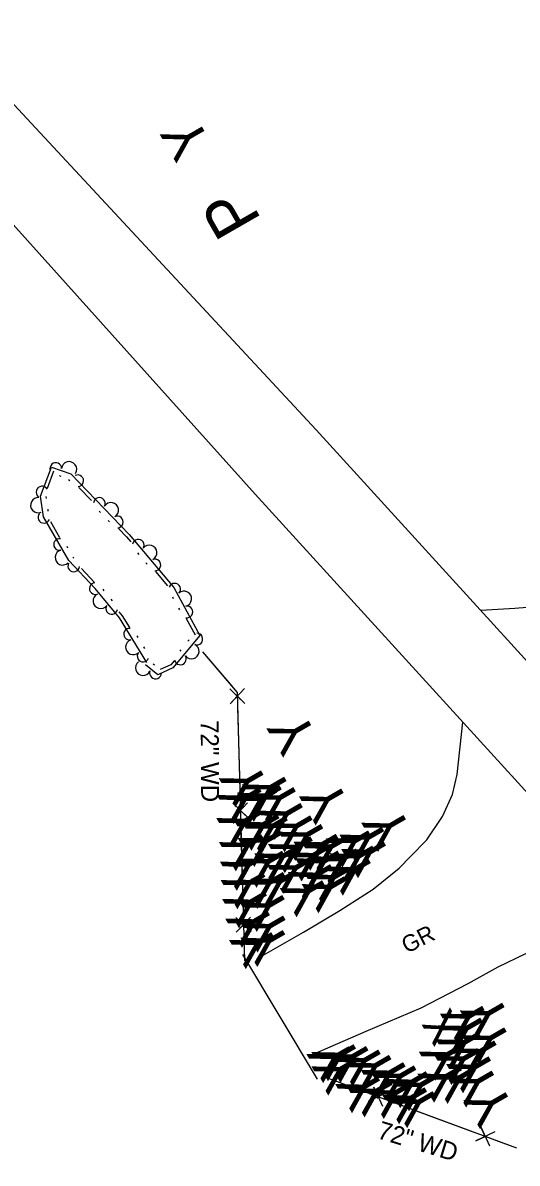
# Model space of a CAD drawing. Extents: x 2030130 to 2036320, y 723205 to 762423.
# Drawn here: x 2034222.4 to 2034332.5, y 759439.7 to 759693.3 of the extents above; entities that cross this region are included whole.
import ezdxf

# ---------------------------------------------------------------- set-up
doc = ezdxf.new("R2010")
doc.units = 0
for name, color, linetype in [('Draft_Station Labels Major', 7, 'Continuous'), ('Draft_Station Tics Major', 7, 'Continuous'), ('Exist Terrain Model Ground Surface', 7, 'Continuous'), ('Old_Level_23', 7, 'Continuous'), ('Old_Level_28', 7, 'Continuous'), ('Prop Horizontal Alignment Ramp', 7, 'Continuous')]:
    doc.layers.add(name, color=color, linetype=linetype)

msp = doc.modelspace()

# ---------------------------------------------------------------- linework, layer by layer
at = {"layer": 'Draft_Station Labels Major'}
for points in [[(2034193.98, 759703.56), (2034287.73, 759602.79), (2034370.61, 759511.86), (2034419.72, 759458.43), (2034445.33, 759432.37), (2034471.55, 759407.33), (2034497.11, 759385.14), (2034517.55, 759368.37), (2034528.08, 759360.37)], [(2034406.4, 759697.05), (2034404.29, 759687.94), (2034402.24, 759679.54), (2034400.98, 759670.76), (2034398.6, 759659.72), (2034394.4, 759646.76), (2034391.51, 759636.74), (2034390.8, 759626.41), (2034391.91, 759617.38), (2034392.01, 759607.6), (2034388.72, 759601.52), (2034384.63, 759597.38), (2034380.26, 759590.7), (2034376.86, 759584.48), (2034371.89, 759577.33), (2034367.26, 759572.7), (2034359.83, 759567.87), (2034353.85, 759564.53), (2034347.15, 759563.4), (2034340.28, 759563.68), (2034331.95, 759563.03), (2034324.37, 759562.59)], [(2034181.13, 759691.91), (2034274.16, 759588.48), (2034357, 759497.6), (2034406.36, 759443.89), (2034432.44, 759417.35), (2034459.25, 759391.75), (2034485.39, 759369.06), (2034506.34, 759351.88), (2034517.18, 759343.65)], [(2034274.47, 759485.08), (2034284.85, 759491.04), (2034292.96, 759495.88), (2034300.4, 759500.6), (2034306.21, 759505.3), (2034308.71, 759507.9), (2034312.37, 759511.61), (2034315.84, 759516.74), (2034318.06, 759521.68), (2034319.08, 759526.13), (2034320.38, 759537.78)], [(2034371.58, 759481.74), (2034358.91, 759486.23), (2034354.02, 759487.37), (2034349.95, 759488.15), (2034345.68, 759488.73), (2034339.79, 759487.64), (2034334.3, 759486.19), (2034328.17, 759483.26), (2034321.51, 759479.53), (2034310.99, 759474.16), (2034298.75, 759468.94), (2034287.34, 759463.98)]]:
    msp.add_lwpolyline(points, dxfattribs=at)
at = {"layer": 'Draft_Station Tics Major'}
for points in [[(2034250.03, 759551.04), (2034243.94, 759560.93), (2034238.53, 759567.45), (2034232.63, 759573.68), (2034227.01, 759583.43), (2034226.35, 759588.02), (2034228.75, 759594.49), (2034233.09, 759593.02), (2034246.09, 759579.5), (2034256, 759567.69), (2034261.77, 759557.02), (2034255.82, 759549.82), (2034252.42, 759548.28), (2034249.68, 759550.49)], [(2034227.88, 759589.8), (2034229.31, 759593.64)], [(2034230.5, 759592.6), (2034230.89, 759592.47)], [(2034232.58, 759591.76), (2034232.87, 759591.47)], [(2034234.87, 759589.98), (2034237.71, 759587.03)], [(2034227.66, 759587.53), (2034227.6, 759587.94)], [(2034228.07, 759584.69), (2034228.01, 759585.1)], [(2034239.41, 759584.67), (2034239.69, 759584.38)], [(2034230.66, 759578.75), (2034228.61, 759582.3)], [(2034241.4, 759582.6), (2034241.69, 759582.31)], [(2034243.69, 759580.82), (2034245.48, 759578.96), (2034246.42, 759577.84)], [(2034232.45, 759576.47), (2034232.24, 759576.82)], [(2034233.78, 759574.26), (2034233.63, 759574.42)], [(2034247.95, 759575.38), (2034248.21, 759575.06)], [(2034249.79, 759573.18), (2034250.06, 759572.86)], [(2034238.27, 759568.92), (2034235.45, 759571.9)], [(2034251.95, 759571.24), (2034254.59, 759568.1)], [(2034240.51, 759566.98), (2034240.25, 759567.3)], [(2034255.7, 759565.65), (2034255.9, 759565.29)], [(2034242.35, 759564.77), (2034242.09, 759565.09)], [(2034257.07, 759563.13), (2034257.26, 759562.77)], [(2034246.21, 759558.81), (2034244.6, 759561.41), (2034243.86, 759562.3)], [(2034258.79, 759560.8), (2034260.75, 759557.19)], [(2034248.06, 759556.58), (2034247.85, 759556.93)], [(2034259.41, 759556.08), (2034259.14, 759555.77)], [(2034249.57, 759554.13), (2034249.35, 759554.48)], [(2034257.58, 759553.87), (2034257.32, 759553.56)], [(2034251.74, 759550.41), (2034251.42, 759550.67)], [(2034256.06, 759551.4), (2034255.31, 759550.49), (2034253, 759549.45)]]:
    msp.add_lwpolyline(points, dxfattribs=at)
for centre, radius, start, end in [((2034229.73, 759594.16), 1.3, 359.6468, 200.4434), ((2034232.71, 759594.01), 1.69, 327.1756, 175.2481), ((2034234.61, 759591.44), 1.3, 274.6697, 115.4663), ((2034226.68, 759588.93), 1.3, 30.4451, 231.2417), ((2034225.81, 759586.02), 1.69, 84.1627, 292.2352), ((2034239.44, 759586.41), 1.3, 332.3362, 173.1327), ((2034242.02, 759584.91), 1.69, 299.865, 147.9375), ((2034227.08, 759583.31), 1.3, 138.4082, 339.2048), ((2034243.42, 759582.28), 1.3, 274.6697, 115.4663), ((2034230.56, 759577.27), 1.3, 80.7418, 281.5383), ((2034248.1, 759577.11), 1.3, 328.4294, 169.2259), ((2034231.28, 759574.38), 1.69, 105.937, 314.0095), ((2034250.57, 759575.44), 1.69, 295.9582, 144.0307), ((2034233.73, 759572.52), 1.3, 151.8397, 352.6363), ((2034251.79, 759572.71), 1.3, 270.7629, 111.5595), ((2034238.52, 759567.46), 1.3, 94.1733, 294.9698), ((2034256.2, 759567.32), 1.3, 316.8309, 157.6275), ((2034239.72, 759564.73), 1.69, 115.6449, 323.7174), ((2034258.29, 759565.19), 1.69, 284.3597, 132.4322), ((2034242.19, 759563.04), 1.3, 148.1161, 348.9127), ((2034258.93, 759562.27), 1.3, 259.1644, 99.961), ((2034246.15, 759557.33), 1.3, 82.3998, 283.1964), ((2034246.96, 759554.45), 1.69, 107.5951, 315.6676), ((2034261.14, 759556.25), 1.3, 248.8652, 89.6617), ((2034249.17, 759552.44), 1.3, 140.0663, 340.8629), ((2034259.94, 759553.51), 1.69, 216.394, 64.4665), ((2034249.17, 759549.84), 1.69, 127.0823, 335.1548), ((2034257.48, 759551.82), 1.3, 191.1987, 31.9953), ((2034251.92, 759548.68), 1.3, 159.5535, 0.3501)]:
    msp.add_arc(centre, radius, start, end, dxfattribs=at)
at = {"layer": 'Exist Terrain Model Ground Surface'}
msp.add_line((2034288.01, 759458.38), (2034271.37, 759486.04), dxfattribs=at)
for points in [[(2034262.41, 759553.4), (2034270.11, 759544.38), (2034271.73, 759484.69)], [(2034262.41, 759553.4), (2034269.07, 759545.6)], [(2034268.45, 759545.13), (2034271.82, 759541.93), (2034270.14, 759543.53), (2034268.54, 759541.85), (2034271.73, 759545.21)], [(2034270.2, 759541.07), (2034270.48, 759530.82)], [(2034270.48, 759530.82), (2034270.76, 759520.57)], [(2034269.14, 759519.71), (2034272.51, 759516.52), (2034270.82, 759518.11), (2034269.23, 759516.43), (2034272.42, 759519.8)], [(2034270.89, 759515.65), (2034271.17, 759505.4)], [(2034271.17, 759505.4), (2034271.45, 759495.16)], [(2034269.83, 759494.29), (2034273.2, 759491.1), (2034271.51, 759492.7), (2034269.92, 759491.01), (2034273.11, 759494.38)], [(2034271.58, 759490.24), (2034271.73, 759484.69)], [(2034289.58, 759458.87), (2034332.32, 759443.05)], [(2034289.58, 759458.87), (2034299.19, 759455.31)], [(2034303.61, 759455.42), (2034299.39, 759453.49), (2034301.5, 759454.46), (2034300.53, 759456.56), (2034302.47, 759452.35)], [(2034303.81, 759453.6), (2034313.42, 759450.04)], [(2034313.42, 759450.04), (2034323.04, 759446.48)], [(2034327.45, 759446.6), (2034323.24, 759444.66), (2034325.35, 759445.63), (2034324.38, 759447.74), (2034326.32, 759443.52)], [(2034327.65, 759444.78), (2034332.32, 759443.05)]]:
    msp.add_lwpolyline(points, dxfattribs=at)

# ---------------------------------------------------------------- texts
at = {"layer": 'Draft_Station Tics Major'}
for s, height, p in [('Y', 9.02, (2034264.55, 759666.27)), ('Y', 9.02, (2034288.32, 759534.12)), ('Y', 9.02, (2034277.7, 759523.06)), ('Y', 9.02, (2034282.85, 759521.66)), ('Y', 9.02, (2034277.27, 759519.32)), ('Y', 9.02, (2034280.72, 759519.09)), ('Y', 9.02, (2034281.78, 759519.81)), ('Y', 9.02, (2034284.9, 759519.35)), ('Y', 9.02, (2034295.55, 759519.03)), ('Y', 9.02, (2034277.16, 759514.19)), ('Y', 9.02, (2034281.25, 759513.4)), ('Y', 9.02, (2034286.46, 759515.83)), ('Y', 9.02, (2034283.12, 759512.91)), ('Y', 9.02, (2034288.63, 759513.06)), ('Y', 9.02, (2034291.01, 759511.14)), ('Y', 9.02, (2034309.43, 759513.14)), ('Y', 9.02, (2034277.77, 759508.84)), ('Y', 9.02, (2034281.9, 759509.79)), ('Y', 9.02, (2034288.68, 759508.4)), ('Y', 9.02, (2034294.34, 759508.96)), ('Y', 9.02, (2034296.36, 759508.5)), ('Y', 9.02, (2034301.54, 759509.71)), ('Y', 9.02, (2034304.57, 759510.51)), ('Y', 9.02, (2034285.61, 759506.35)), ('Y', 9.02, (2034292.41, 759506.57)), ('Y', 9.02, (2034302.45, 759506.33)), ('Y', 9.02, (2034304.97, 759507.3)), ('Y', 9.02, (2034277.98, 759504.49)), ('Y', 9.02, (2034282.37, 759505.18)), ('Y', 9.02, (2034288.46, 759503.79)), ('Y', 9.02, (2034294.74, 759505.23)), ('Y', 9.02, (2034298.81, 759505.67)), ('Y', 9.02, (2034301.6, 759503.42)), ('Y', 9.02, (2034284.94, 759500.76)), ('Y', 9.02, (2034293.08, 759502.2)), ('Y', 9.02, (2034296.92, 759501.67)), ('Y', 9.02, (2034278.12, 759500.4)), ('Y', 9.02, (2034282.57, 759500.47)), ('Y', 9.02, (2034291.3, 759498.62)), ('Y', 9.02, (2034296.17, 759499.5)), ('Y', 9.02, (2034278.46, 759496.2)), ('Y', 9.02, (2034282.44, 759495.36)), ('Y', 9.02, (2034279.14, 759491.83)), ('Y', 9.02, (2034282.62, 759490.78)), ('Y', 9.02, (2034279.99, 759487.08)), ('Y', 9.02, (2034282.55, 759487.55)), ('X', 7.38, (2034320.65, 759468.82)), ('Y', 9.02, (2034326.94, 759470.7)), ('Y', 9.02, (2034331.39, 759471.39)), ('Y', 9.02, (2034326.52, 759468.08)), ('Y', 9.02, (2034331.84, 759465.91)), ('Y', 9.02, (2034326.05, 759464.96)), ('Y', 9.02, (2034329.61, 759462.99)), ('Y', 9.02, (2034297.22, 759461.72)), ('Y', 9.02, (2034298.3, 759462.16)), ('Y', 9.02, (2034301.07, 759461.76)), ('Y', 9.02, (2034303.8, 759460.97)), ('Y', 9.02, (2034322.24, 759462.25)), ('Y', 9.02, (2034325.8, 759461.29)), ('Y', 9.02, (2034298.36, 759458.95)), ('Y', 9.02, (2034306.19, 759459.79)), ('Y', 9.02, (2034309.34, 759458.17)), ('Y', 9.02, (2034328.36, 759459.47)), ('Y', 9.02, (2034303.64, 759455.04)), ('Y', 9.02, (2034311.73, 759457.45)), ('Y', 9.02, (2034314.38, 759456.16)), ('Y', 9.02, (2034316.32, 759455.49)), ('Y', 9.02, (2034321.91, 759457.36)), ('Y', 9.02, (2034324.92, 759457.1)), ('Y', 9.02, (2034329.05, 759456.29)), ('Y', 9.02, (2034306.44, 759454.11)), ('Y', 9.02, (2034310.72, 759453.75)), ('Y', 9.02, (2034314.13, 759452.58)), ('Y', 9.02, (2034315.91, 759451.72)), ('Y', 9.02, (2034332.15, 759451.48))]:
    msp.add_text(s, height=height, rotation=119.9336, dxfattribs=at).set_placement(p)
at = {"layer": 'Old_Level_23'}
msp.add_text('GR', height=3.691, rotation=26.5268, dxfattribs=at).set_placement((2034307.88, 759486.22))
at = {"layer": 'Old_Level_28'}
for rotation, p in [(270.3424, (2034262, 759538.2)), (343.1346, (2034301.08, 759445.28))]:
    msp.add_text('72" WD', height=4, rotation=rotation, dxfattribs=at).set_placement(p)
at = {"layer": 'Prop Horizontal Alignment Ramp'}
msp.add_text('P', height=10.66, rotation=119.9336, dxfattribs=at).set_placement((2034275.65, 759649.45))

doc.saveas('drawing.dxf')
